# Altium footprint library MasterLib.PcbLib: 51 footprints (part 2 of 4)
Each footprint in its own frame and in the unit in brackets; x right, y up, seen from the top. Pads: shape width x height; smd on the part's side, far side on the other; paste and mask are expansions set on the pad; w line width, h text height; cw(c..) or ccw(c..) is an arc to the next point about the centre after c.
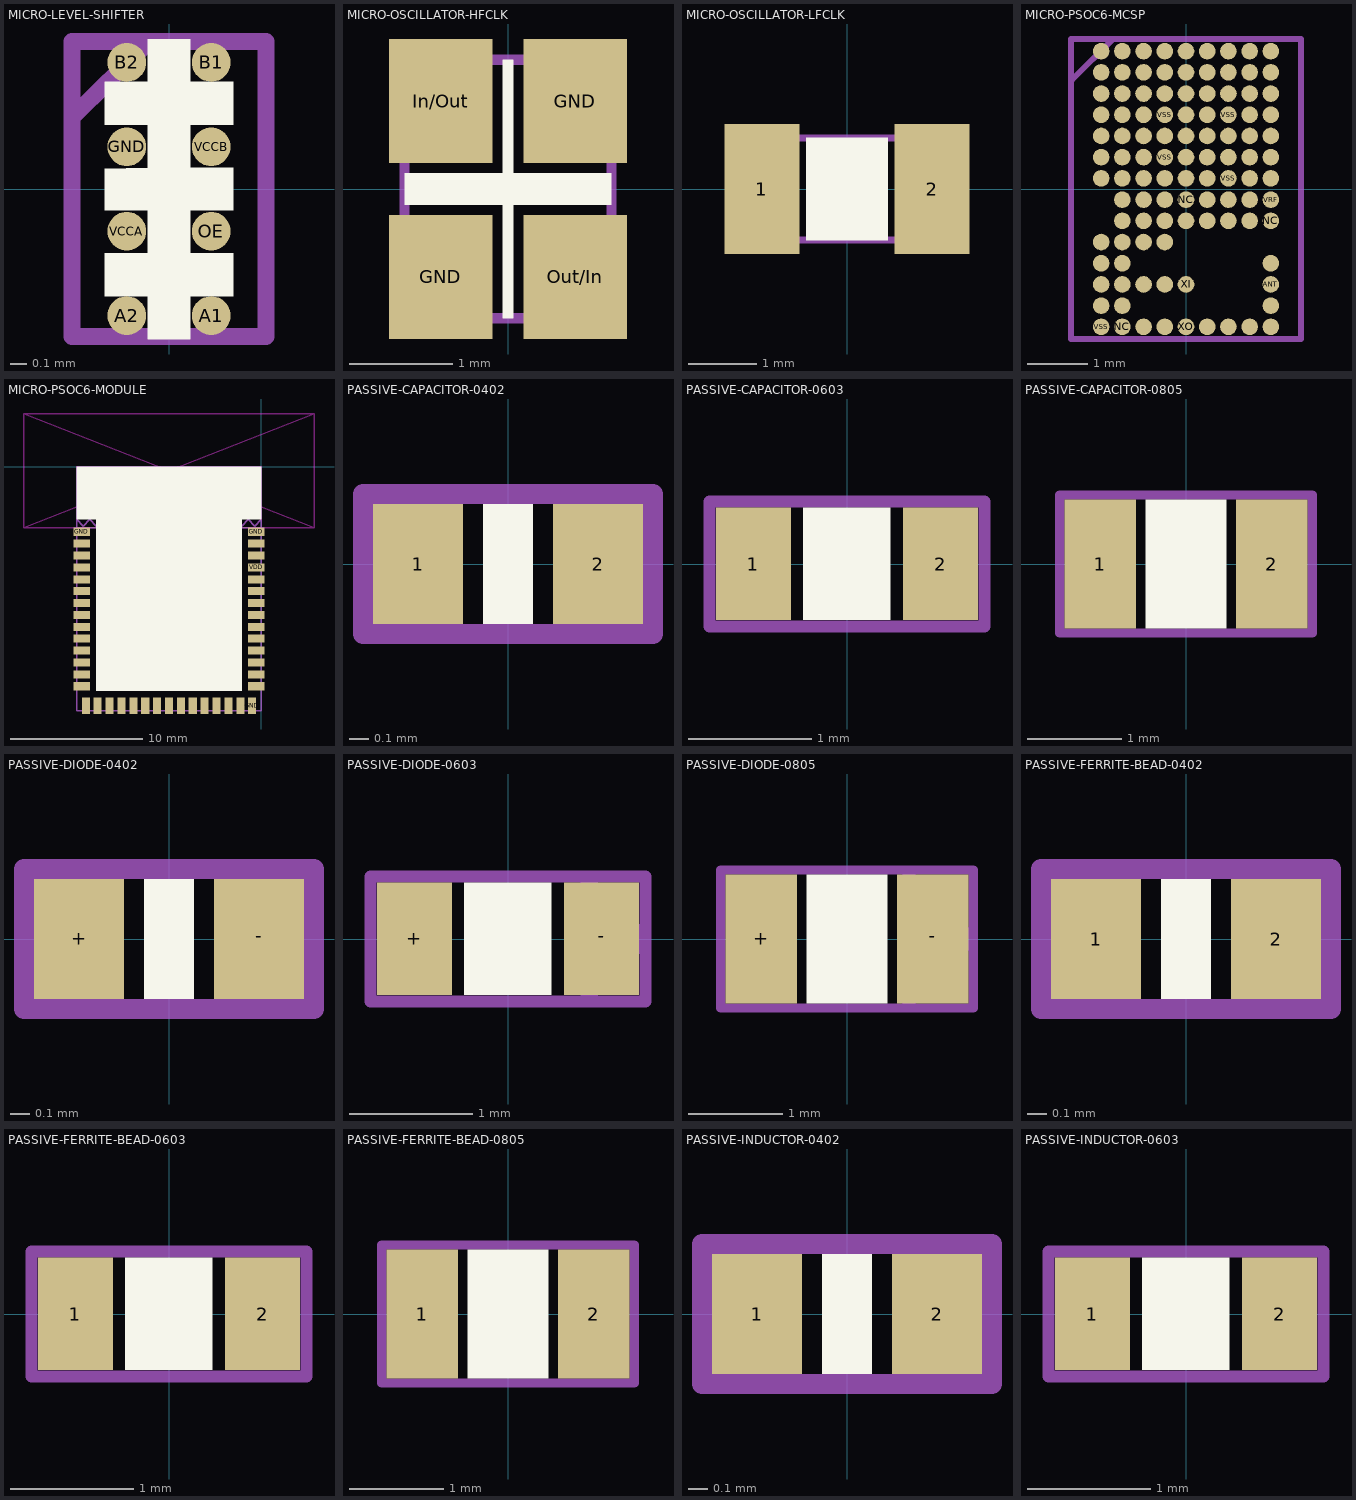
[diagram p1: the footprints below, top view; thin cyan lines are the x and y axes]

## MICRO-LEVEL-SHIFTER [mm]
pads (8):
  round 0.23 smd: A1(0.25,-0.75) A2(-0.25,-0.75) B1(0.25,0.75) B2(-0.25,0.75) GND(-0.25,0.25) OE(0.25,-0.25) VCCA(-0.25,-0.25) VCCB(0.25,0.25)
Top Layer:
  region: -0.127,0.889
Top Overlay:
  region: -0.127,0.889 0.127,0.889 0.127,0.635 0.381,0.635 0.381,0.381 0.127,0.381 0.127,0.127 0.381,0.127 0.381,-0.127 0.127,-0.127 0.127,-0.381 0.381,-0.381 0.381,-0.635 0.127,-0.635 0.127,-0.889 -0.127,-0.889 -0.127,-0.635 -0.381,-0.635 -0.381,-0.381 -0.127,-0.381 -0.127,-0.127 -0.381,-0.127 -0.381,0.119 -0.127,0.127 -0.127,0.381 -0.381,0.381 -0.381,0.635 -0.127,0.635
Assembly Top:
  lines w0.1: -0.575,0.425 -0.127,0.865 ; -0.575,-0.875 0.575,-0.875 0.575,0.875 -0.575,0.875 -0.575,-0.875
  text ".Designator" at 0.2,-0.6 h0.4
3D body "MICRO-LEVEL-SHIFTER.step": height 0.42, standoff -0.07, extent -0.459,-0.959 0.459,0.959

## MICRO-OSCILLATOR-HFCLK [mm]
height 0.5
pads (4):
  rect 1x1.2 smd: GND(-0.65,-0.85) GND(0.65,0.85) In/Out(-0.65,0.85) Out/In(0.65,-0.85)
Top Overlay:
  region: -0.05,1.25 0.05,1.25 0.05,0.15 1,0.15 1,-0.15 0.05,-0.15 0.05,-1.25 -0.05,-1.25 -0.05,-0.15 -1,-0.15 -1,0.15 -0.05,0.15
Assembly Top:
  lines w0.1: -0.991,0.737 -0.483,1.245 ; -1,-1.25 1,-1.25 1,1.25 -1,1.25 -1,-1.25
  text ".Designator" at 0.2,-0.6 h0.4
3D body "MICRO-OSCILLATOR-24MHZ.step": height 0.45, standoff -0.06, extent -1.05,-1.3 1.05,1.3

## MICRO-OSCILLATOR-LFCLK [mm]
height 0.9
pads (2):
  rect 1.1x1.9 smd: 1(-1.25,0) 2(1.25,0)
Top Overlay:
  region: -0.6,0.75 0.6,0.75 0.6,-0.75 -0.6,-0.75
Assembly Top:
  lines w0.1: -1.6,0.25 -1.1,0.75 ; -1.6,-0.75 -1.6,0.75 1.6,0.75 1.6,-0.75 -1.6,-0.75
  text ".Designator" at -0.4,-0.2 h0.4
3D body "MICRO-OSCILLATOR-LFCLK.step": height 0.85, standoff -0.05, extent -1.6,-0.75 1.6,0.75

## MICRO-PSOC6-MCSP [mm]
height 0.65
pads (104):
  round 0.275 smd: ANT(1.4,-1.575) DVDD(-0.35,-1.575) NC(-1.05,-2.275) NC(0,-0.175) NC(1.4,-0.525) P0.0(1.05,1.225) P0.1(0.35,0.875) P0.2(1.4,1.225) P0.3(0.7,0.875) P0.4(1.05,0.875) P0.5(1.4,0.875) P1.0(0,0.525) P1.1(0.35,0.525) P1.3(1.4,0.525) P1.4(1.05,0.525) P1.5(0.7,0.525) P5.0(0.7,-0.525) P5.1(0,-0.525) P5.2(0.35,-0.525) P5.3(0.7,-0.175) P5.4(0.35,-0.175) P5.5(-0.35,-0.525) P5.6(-0.7,-0.875) P5.7(-0.35,-0.875) P6.0(-0.7,-0.525) P6.1(-1.05,-0.875) P6.2(-1.05,-1.575) P6.3(-1.4,-1.225) P6.4(-1.05,-0.525) P6.5(-1.4,-0.875) P6.6(-1.05,-1.925) P6.7(-1.4,-1.575) P7.0(-1.4,-1.925) P7.1(0.35,0.175) P7.2(-0.35,-0.175) P7.3(0,0.175) P7.4(-0.7,-0.175) P7.5(-1.05,-0.175) P7.6(-0.7,0.175) P7.7(-1.05,0.175) P8.0(-0.35,0.175) P8.1(-1.4,0.175) P8.2(-0.7,0.525) P8.3(-1.05,0.525) P8.4(-1.4,0.525) P8.5(-0.7,0.875) P8.6(-1.4,0.875) P8.7(-1.05,0.875) P9.0(-1.05,1.225) P9.1(-1.4,1.575) P9.2(-0.7,1.225) P9.3(-1.4,1.925) P10.0(-1.05,1.575) P10.1(-1.05,1.925) P10.2(-0.7,1.575) P10.3(-0.35,0.875) P10.4(-1.05,2.275) P10.5(-0.7,2.275) P10.6(0,1.225) P10.7(-0.7,1.925) P11.0(-0.35,1.575) P11.1(0,1.575) P11.2(0.35,1.225) P11.3(-0.35,1.925) P11.4(-0.35,2.275) P11.5(0,1.925) P11.6(0,2.275) P11.7(0.35,2.275) P12.0(0.7,1.925) P12.1(0.7,2.275) P12.2(1.05,1.925) P12.3(1.05,2.275) P12.4(1.05,1.575) P13.0(1.4,2.275) P13.1(1.4,1.925) VBACKUP(1.4,1.575) VBUCK1(1.05,-0.525) VCCD(0.7,1.575) VDCDC(-0.35,-2.275) VDD_NS(1.4,0.175) VDDA(-1.4,2.275) VDDD(0.35,1.575) VDDIO0(0.35,1.925) VDDIO1(-1.4,1.225) VDDR1(1.4,-1.225) VDDR2(1.4,-2.275) VDDR3(1.05,-2.275) VDDR_HVL(-1.05,-1.225) VIND1(1.05,0.175) VIND2(1.05,-0.175) VRF(1.4,-0.175) VSS(-1.4,-2.275) VSS(-0.35,0.525) VSS(-0.35,1.225) VSS(0.7,0.175) VSS(0.7,1.225) VSSR(-0.7,-2.275) VSSR(-0.7,-1.575) VSSR(0.35,-2.275) VSSR(0.7,-2.275) VSSR(1.4,-1.925) XI(0,-1.575) XO(0,-2.275) XRES(0,0.875)
Assembly Top:
  lines w0.1: -1.881,1.803 -1.22,2.464 ; -1.896,-2.475 1.896,-2.475 1.896,2.475 -1.896,2.475 -1.896,-2.475
  text ".Designator" at -0.6,-0.2 h0.4
3D body "MICRO-PSOC6-MCSP.step": height 0.57, standoff -0.06, extent -1.896,-2.495 1.904,2.505

## MICRO-PSOC6-MODULE [mm]
height 2
pads (43):
  rect 1.27x0.61 smd: GND(-13.62,-4.93) GND(-0.38,-4.93) P0.0(-0.38,-8.54) P0.1(-0.38,-9.44) P0.4(-13.62,-6.73) P0.5(-0.38,-5.83) P5.0(-13.62,-8.54) P5.1(-13.62,-7.63) P5.2(-13.62,-9.44) P5.3(-13.62,-10.34) P5.5(-13.62,-11.24) P5.6(-13.62,-14.85) P6.3(-13.62,-16.65) P7.7(-13.62,-15.75) P9.3(-0.38,-12.14) P9.4(-0.38,-16.65) P10.0(-0.38,-15.75) P10.1(-0.38,-14.85) P10.2(-13.62,-13.95) P10.3(-0.38,-10.34) P10.4(-0.38,-11.24) P10.5(-0.38,-13.95) P10.6(-0.38,-13.04) P12.6(-13.62,-13.04) P12.7(-13.62,-12.14) VBACKUP(-0.38,-6.73) VDD(-0.38,-7.63) XRES(-13.62,-5.83)
  rect 0.61x1.27 smd: GND(-0.69,-18.12) P5.4(-9.7,-18.12) P6.2(-12.41,-18.12) P6.4(-8.8,-18.12) P6.5(-13.31,-18.12) P6.6(-11.51,-18.12) P6.7(-10.61,-18.12) P7.1(-7.9,-18.12) P7.2(-7,-18.12) P9.0(-2.49,-18.12) P9.1(-3.39,-18.12) P9.2(-6.1,-18.12) P9.5(-4.29,-18.12) P9.6(-5.2,-18.12) VREF(-1.59,-18.12)
Top Overlay:
  region: -12.5,-17 -1.5,-17 -1.5,-4 0,-4 0,0 -14,0 -14,-4 -12.5,-4
Keep-Out Layer:
  lines w0.1: -18,-4.62 4,-4.62 ; -18,-4.62 -18,4 ; -18,-4.62 4,4 ; -18,4 4,4 ; -18,4 4,-4.62 ; 4,-4.62 4,4
Assembly Top:
  lines w0.1: -14,-4.62 0,-4.62 ; -14,0 -14,-18.5 0,-18.5 0,0 ; -14,0 0,0 ; -14,0 -11,-3 ; -13,-4 -13.5,-4.5 -14,-4 -11,-1 ; -13,-4 -12.5,-4.5 -12,-4 ; -13,-4 -11,-2 ; -13,-4 -14,-3 -11,0 -7,-4 ; -12,-4 -11.5,-4.5 -11,-4 ; -12,-4 -14,-2 -12,0 -11,-1 ; -12,-4 -11,-3 ; -11,-4 -10.5,-4.5 -10,-4 ; -11,-4 -7,0 -3,-4 ; -11,-4 -14,-1 -13,0 -11,-2 ; -11,-3 -10,-4 ; -11,-3 -8,0 -4,-4 ; -11,-2 -9,-4 ; -11,-2 -9,0 -5,-4 ; -11,-1 -8,-4 ; -11,-1 -10,0 -6,-4 ; -10,-4 -9.5,-4.5 -9,-4 ; -10,-4 -6,0 -2,-4 ; -9,-4 -8.5,-4.5 -8,-4 ; -9,-4 -5,0 -1,-4 ; -8,-4 -7.5,-4.5 -7,-4 ; -8,-4 -4,0 0,-4 -0.5,-4.5 -1,-4 ; -7,-4 -6.5,-4.5 -6,-4 ; -7,-4 -3,0 0,-3 -1,-4 ; -6,-4 -5.5,-4.5 -5,-4 ; -6,-4 -2,0 0,-2 -2,-4 ; -5,-4 -4.5,-4.5 -4,-4 ; -5,-4 -1,0 0,-1 -3,-4 ; -4,-4 -3.5,-4.5 -3,-4 ; -4,-4 0,0 ; -3,-4 -2.5,-4.5 -2,-4 ; -2,-4 -1.5,-4.5 -1,-4
  text ".Designator" at -8.5,-9.25 h0.4
3D body "MICRO-PSOC6-MODULE.step": height 2.01, standoff -0.09, extent -14.305,-18.801 0.305,0.004

## PASSIVE-CAPACITOR-0402 [mil]
pads (2):
  rect 18x24 smd: 1(-18,0) 2(18,0)
Top Overlay:
  rectangle: -5,-12 5,12
Assembly Top:
  lines w3.94: -29,-14 -29,14 29,14 29,-14 -29,-14
  text ".Designator" at -23.62,-7.87 h15.75
3D body "PASSIVE-CAPACITOR-0402.step": height 16.34, standoff -3.34, extent -19.68,-13.78 19.69,13.78

## PASSIVE-CAPACITOR-0603 [mil]
pads (2):
  rect 24x36 smd: 1(-30,0) 2(30,0)
Top Overlay:
  rectangle: -14,-18 14,18
Assembly Top:
  lines w3.94: -44,-20 -44,20 44,20 44,-20 -44,-20
  text ".Designator" at -23.62,-7.87 h15.75
3D body "PASSIVE-CAPACITOR-0603.step": height 27.75, standoff -3.75, extent -31.5,-19.69 31.5,19.69

## PASSIVE-CAPACITOR-0805 [mil]
pads (2):
  rect 30x54 smd: 1(-36,0) 2(36,0)
Top Overlay:
  rectangle: -17,-27 17,27
Assembly Top:
  lines w3.94: -53,-29 53,-29 53,29 -53,29 -53,-29
  text ".Designator" at -23.62,-7.87 h15.75
3D body "PASSIVE-CAPACITOR-0805.step": height 45.61, standoff -3.61, extent -39.37,-25.59 39.37,25.59

## PASSIVE-DIODE-0402 [mil]
pads (2):
  rect 18x24 smd: +(-18,0) -(18,0)
Top Overlay:
  rectangle: -5,-12 5,12
Assembly Top:
  lines w3.94: 15,-14 29,0 15,14 ; -29,-14 -29,14 29,14 29,-14 -29,-14
  text ".Designator" at -23.62,-7.87 h15.75
3D body "PASSIVE-DIODE-0402.step": height 12.75, standoff -3, extent -19.68,-9.84 19.69,9.85

## PASSIVE-DIODE-0603 [mil]
pads (2):
  rect 24x36 smd: +(-30,0) -(30,0)
Top Overlay:
  rectangle: -14,-18 14,18
Assembly Top:
  lines w3.94: 24,-20 44,0 24,20 ; -44,-20 44,-20 44,20 -44,20 -44,-20
  text ".Designator" at -23.62,-7.87 h15.75
3D body "PASSIVE-DIODE-0603.step": height 20.62, standoff -3, extent -31.49,-15.74 31.5,15.75

## PASSIVE-DIODE-0805 [mil]
pads (2):
  rect 30x54 smd: +(-36,0) -(36,0)
Top Overlay:
  rectangle: -17,-27 17,27
Assembly Top:
  lines w3.94: 24,-29 53,0 24,29 ; -53,-29 -53,29 53,29 53,-29 -53,-29
  text ".Designator" at -23.62,-7.87 h15.75
3D body "PASSIVE-DIODE-0805.step": height 28.5, standoff -3, extent -39.37,-24.6 39.37,24.61

## PASSIVE-FERRITE-BEAD-0402 [mil]
pads (2):
  rect 18x24 smd: 1(-18,0) 2(18,0)
Top Overlay:
  rectangle: -5,-12 5,12
Assembly Top:
  lines w3.94: -29,-14 -29,14 29,14 29,-14 -29,-14
  text ".Designator" at -23.62,-7.87 h15.75
3D body "PASSIVE-FERRITE-BEAD-0402.step": height 16.84, standoff -2.84, extent -19.68,-9.84 19.69,9.85

## PASSIVE-FERRITE-BEAD-0603 [mil]
pads (2):
  rect 24x36 smd: 1(-30,0) 2(30,0)
Top Overlay:
  rectangle: -14,-18 14,18
Assembly Top:
  lines w3.94: -44,-20 -44,20 44,20 44,-20 -44,-20
  text ".Designator" at -23.62,-7.87 h15.75
3D body "PASSIVE-FERRITE-BEAD-0603.step": height 28.75, standoff -2.75, extent -31.49,-12.79 31.5,12.8

## PASSIVE-FERRITE-BEAD-0805 [mil]
pads (2):
  rect 30x54 smd: 1(-36,0) 2(36,0)
Top Overlay:
  rectangle: -17,-27 17,27
Assembly Top:
  lines w3.94: -53,-29 53,-29 53,29 -53,29 -53,-29
  text ".Designator" at -23.62,-7.87 h15.75
3D body "PASSIVE-FERRITE-BEAD-0805.step": height 46.61, standoff -2.61, extent -39.37,-16.73 39.37,16.74

## PASSIVE-INDUCTOR-0402 [mil]
pads (2):
  rect 18x24 smd: 1(-18,0) 2(18,0)
Top Overlay:
  rectangle: -5,-12 5,12
Assembly Top:
  lines w3.94: -29,-14 29,-14 29,14 -29,14 -29,-14
  text ".Designator" at -23.62,-7.87 h15.75
3D body "PASSIVE-INDUCTOR-0402.step": height 15.84, standoff -3.84, extent -19.68,-11.81 19.69,11.81

## PASSIVE-INDUCTOR-0603 [mil]
pads (2):
  rect 24x36 smd: 1(-30,0) 2(30,0)
Top Overlay:
  rectangle: -14,-18 14,18
Assembly Top:
  lines w3.94: -44,-20 -44,20 44,20 44,-20 -44,-20
  text ".Designator" at -23.62,-7.87 h15.75
3D body "PASSIVE-INDUCTOR-0603.step": height 28.75, standoff -2.75, extent -31.5,-17.72 31.5,17.72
